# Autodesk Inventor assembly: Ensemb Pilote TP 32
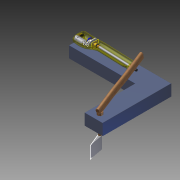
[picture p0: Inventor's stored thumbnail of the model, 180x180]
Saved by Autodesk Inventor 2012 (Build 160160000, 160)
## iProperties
Created: 2013-10
Part Number: Ensemb Pilote TP 32
Document SubType Name: Assembly
Designer: Bernard QUIVRIN
Author: Bernard QUIVRIN
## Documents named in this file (8)
- C:\Users\QUIVRIN\Documents\Clos Maire\T S SI\TP\TP transmission de puissance\Pilote électrique de bateau\TP pilote électrique\inventor2012-TP32\Ensemb Pilote TP 32 SD.iam
- C:\Users\QUIVRIN\Documents\Clos Maire\T S SI\TP\TP transmission de puissance\Pilote électrique de bateau\TP pilote électrique\inventor2012-TP32\banc.ipt
- C:\Users\QUIVRIN\Documents\Clos Maire\T S SI\TP\TP transmission de puissance\Pilote électrique de bateau\TP pilote électrique\inventor2012-TP32\Ensemble_Safran_Barre.iam
- C:\Users\QUIVRIN\Documents\Clos Maire\T S SI\TP\TP transmission de puissance\Pilote électrique de bateau\TP pilote électrique\inventor2012-TP32\Ensemble_Corps.iam
- C:\Users\QUIVRIN\Documents\Clos Maire\T S SI\TP\TP transmission de puissance\Pilote électrique de bateau\TP pilote électrique\inventor2012-TP32\Ensemble_Axe_fixation.iam
- C:\Users\QUIVRIN\Documents\Clos Maire\T S SI\TP\TP transmission de puissance\Pilote électrique de bateau\TP pilote électrique\inventor2012-TP32\Ensemble_Axe_moteur.iam
- C:\Users\QUIVRIN\Documents\Clos Maire\T S SI\TP\TP transmission de puissance\Pilote électrique de bateau\TP pilote électrique\inventor2012-TP32\Ensemble_Vis_d'entraînement.iam
- C:\Users\QUIVRIN\Documents\Clos Maire\T S SI\TP\TP transmission de puissance\Pilote électrique de bateau\TP pilote électrique\inventor2012-TP32\Ensemble_Tige.iam
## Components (7 placed, 7 different names)
1. banc:1 — Logement:1, Affleurement:1, Plaquage:1, Angle:1
2. Ensemble_Safran_Barre:1 [sub-assembly] — Logement:1, Plaquage:12
3. Ensemble_Corps:1 [sub-assembly] — Plaquage:3, Plaquage:4, Plaquage:5, Plaquage:6, Plaquage:7, Plaquage:8, Plaquage:9
4. Ensemble_Axe_fixation:1 [sub-assembly] — Affleurement:1, Plaquage:1, Plaquage:3, Plaquage:4
5. Ensemble_Axe_moteur:1 [sub-assembly] — Plaquage:5, Plaquage:6
6. Ensemble_Vis_d'entraînement:1 [sub-assembly] — Plaquage:7, Plaquage:8, Plaquage:10, Plaquage:11
7. Ensemble_Tige:1 [sub-assembly] — Plaquage:9, Plaquage:10, Plaquage:11, Angle:1, Plaquage:12
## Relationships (14: Mate 11, Insert 1, Flush 1, Angle 1)
- Logement:1 [Insert]: banc:1 ↔ Ensemble_Safran_Barre:1
- Affleurement:1 [Flush]: banc:1 ↔ Ensemble_Axe_fixation:1
- Plaquage:1 [Mate]: banc:1 ↔ Ensemble_Axe_fixation:1
- Plaquage:3 [Mate]: Ensemble_Corps:1 ↔ Ensemble_Axe_fixation:1
- Plaquage:4 [Mate]: Ensemble_Corps:1 ↔ Ensemble_Axe_fixation:1
- Plaquage:5 [Mate]: Ensemble_Corps:1 ↔ Ensemble_Axe_moteur:1
- Plaquage:6 [Mate]: Ensemble_Corps:1 ↔ Ensemble_Axe_moteur:1
- Plaquage:7 [Mate]: Ensemble_Corps:1 ↔ Ensemble_Vis_d'entraînement:1
- Plaquage:8 [Mate]: Ensemble_Corps:1 ↔ Ensemble_Vis_d'entraînement:1
- Plaquage:9 [Mate]: Ensemble_Corps:1 ↔ Ensemble_Tige:1
- Plaquage:10 [Mate]: Ensemble_Vis_d'entraînement:1 ↔ Ensemble_Tige:1
- Plaquage:11 [Mate]: Ensemble_Vis_d'entraînement:1 ↔ Ensemble_Tige:1
- Angle:1: banc:1 ↔ Ensemble_Tige:1
- Plaquage:12 [Mate]: Ensemble_Safran_Barre:1 ↔ Ensemble_Tige:1
